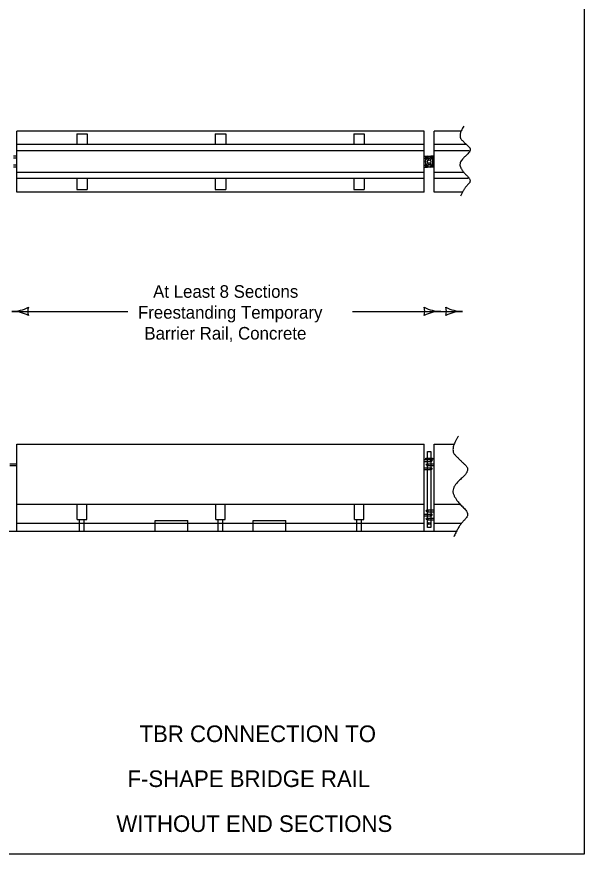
# Model space of a CAD drawing. Extents: x 10028 to 81668, y 3581 to 11018.
# Drawn here: x 16183 to 16868, y 7924 to 8934 of the extents above; entities that cross this region are included whole.
import ezdxf

# ---------------------------------------------------------------- set-up
doc = ezdxf.new("R2010")
doc.units = 0
for name, color, linetype in [('dsnCellsNorthArrow', 7, 'Continuous'), ('dsnTextTabulation', 7, 'Continuous'), ('Level 41', 7, 'Continuous'), ('Level 9', 7, 'Continuous'), ('SheetBorder', 7, 'Continuous')]:
    doc.layers.add(name, color=color, linetype=linetype)

msp = doc.modelspace()

# ---------------------------------------------------------------- linework, layer by layer
at = {"layer": 'dsnTextTabulation'}
for p, q in [((16674.6, 8796.1), (16183.1, 8796.1)), ((16183.1, 8722.4), (16183.1, 8796.1)), ((16674.6, 8722.4), (16674.6, 8796.1)), ((16719.2, 8796.1), (16686.5, 8796.1)), ((16686.5, 8722.4), (16686.5, 8796.1)), ((16674.6, 8779.8), (16183.1, 8779.8)), ((16725.7, 8779.8), (16686.5, 8779.8)), ((16674.6, 8772.4), (16183.1, 8772.4)), ((16728.6, 8772.4), (16686.5, 8772.4)), ((16674.6, 8746.2), (16183.1, 8746.2)), ((16674.6, 8738.8), (16183.1, 8738.8)), ((16722.7, 8746.2), (16686.5, 8746.2)), ((16727.7, 8738.8), (16686.5, 8738.8)), ((16674.6, 8722.4), (16183.1, 8722.4)), ((16720.8, 8722.4), (16686.5, 8722.4)), ((16177.1, 8578.7), (16317, 8578.7)), ((16588, 8578.7), (16720.5, 8578.7)), ((16183.1, 8313.9), (16183.1, 8418.5)), ((16183.1, 8418.5), (16674.6, 8418.5)), ((16674.6, 8313.9), (16674.6, 8418.5)), ((16686.5, 8313.9), (16686.5, 8418.5)), ((16686.5, 8418.5), (16710.9, 8418.5)), ((16183.1, 8346.4), (16674.6, 8346.4)), ((16686.5, 8346.4), (16717.9, 8346.4)), ((16183.1, 8323.4), (16674.6, 8323.4)), ((16350.2, 8326.7), (16389.5, 8326.7)), ((16350.2, 8313.6), (16350.2, 8323.4)), ((16389.5, 8313.6), (16389.5, 8323.4)), ((16468.1, 8326.7), (16507.5, 8326.7)), ((16468.1, 8313.6), (16468.1, 8323.4)), ((16507.5, 8313.6), (16507.5, 8323.4)), ((16686.5, 8323.4), (16719.4, 8323.4)), ((16183.3, 8313.6), (16350.2, 8313.6)), ((16389.5, 8313.6), (16468.1, 8313.6)), ((16507.5, 8313.6), (16674.3, 8313.6)), ((16686.7, 8313.6), (16713.5, 8313.6))]:
    msp.add_line(p, q, dxfattribs=at)
for centre, radius, start, end in [((16177.1, 8621.2), 42.5, 270, 298.0725), ((16177.1, 8536.2), 42.5, 61.9275, 90), ((16212.8, 8578.7), 16.4, 162.2666, 197.7334), ((16658.7, 8578.7), 16.4, 342.2666, 17.7333), ((16694.4, 8621.2), 42.5, 241.9275, 270), ((16694.4, 8536.2), 42.5, 90, 118.0725), ((16684.8, 8578.7), 16.4, 342.2666, 17.7333), ((16720.5, 8621.2), 42.5, 241.9275, 270), ((16720.5, 8536.2), 42.5, 90, 118.0725)]:
    msp.add_arc(centre, radius, start, end, dxfattribs=at)
at = {"layer": 'Level 41'}
for p, q in [((16255.4, 8793), (16268, 8793)), ((16255.4, 8793), (16255.4, 8779.8)), ((16268, 8793), (16268, 8779.8)), ((16422.5, 8793), (16435.1, 8793)), ((16422.5, 8793), (16422.5, 8779.8)), ((16435.1, 8793), (16435.1, 8779.8)), ((16589.7, 8793), (16589.7, 8779.8)), ((16589.7, 8793), (16602.2, 8793)), ((16602.2, 8793), (16602.2, 8779.8)), ((16183.1, 8766), (16179.1, 8766)), ((16183.1, 8763.6), (16179.1, 8763.6)), ((16674.6, 8766), (16678.5, 8766)), ((16674.6, 8763.6), (16678.5, 8763.6)), ((16686.5, 8766), (16682.5, 8766)), ((16686.5, 8763.6), (16682.5, 8763.6)), ((16183.1, 8755), (16179.1, 8755)), ((16183.1, 8752.6), (16179.1, 8752.6)), ((16674.6, 8755), (16678.5, 8755)), ((16674.6, 8752.6), (16678.5, 8752.6)), ((16686.5, 8755), (16682.5, 8755)), ((16686.5, 8752.6), (16682.5, 8752.6)), ((16255.4, 8738.8), (16255.4, 8725.5)), ((16268, 8738.8), (16268, 8725.5)), ((16422.5, 8738.8), (16422.5, 8725.5)), ((16435.1, 8738.8), (16435.1, 8725.5)), ((16589.7, 8738.8), (16589.7, 8725.5)), ((16602.2, 8738.8), (16602.2, 8725.5)), ((16255.4, 8725.5), (16268, 8725.5)), ((16422.5, 8725.5), (16435.1, 8725.5)), ((16589.7, 8725.5), (16602.2, 8725.5)), ((16174.6, 8394.9), (16183.1, 8394.9)), ((16674.6, 8399.9), (16683.1, 8399.9)), ((16674.6, 8397.7), (16683.1, 8397.7)), ((16678, 8394.9), (16686.5, 8394.9)), ((16174.6, 8392.8), (16183.1, 8392.8)), ((16674.6, 8390), (16683.1, 8390)), ((16674.6, 8387.9), (16683.1, 8387.9)), ((16678, 8392.8), (16686.5, 8392.8)), ((16256, 8327.8), (16256, 8346.4)), ((16267.4, 8327.8), (16267.4, 8346.4)), ((16423.2, 8327.8), (16423.2, 8346.4)), ((16434.5, 8327.8), (16434.5, 8346.4)), ((16590.3, 8327.8), (16590.3, 8346.4)), ((16601.6, 8327.8), (16601.6, 8346.4)), ((16674.6, 8334.3), (16683.1, 8334.3)), ((16678, 8339.2), (16686.5, 8339.2)), ((16678, 8337.1), (16686.5, 8337.1)), ((16256, 8327.8), (16267.4, 8327.8)), ((16258.9, 8313.6), (16258.9, 8327.8)), ((16264.5, 8313.6), (16264.5, 8327.8)), ((16423.2, 8327.8), (16434.5, 8327.8)), ((16426, 8313.6), (16426, 8327.8)), ((16431.7, 8313.6), (16431.7, 8327.8)), ((16590.3, 8327.8), (16601.6, 8327.8)), ((16593.1, 8313.6), (16593.1, 8327.8)), ((16598.8, 8313.6), (16598.8, 8327.8)), ((16674.6, 8332.2), (16683.1, 8332.2)), ((16678, 8329.4), (16686.5, 8329.4)), ((16678, 8327.3), (16686.5, 8327.3))]:
    msp.add_line(p, q, dxfattribs=at)
for centre in [(16678, 8393.9), (16683.1, 8398.8), (16683.1, 8389), (16678, 8338.2), (16683.1, 8333.3), (16678, 8328.4)]:
    msp.add_circle(centre, 1.06, dxfattribs=at)
for centre, radius, start, end in [((16682.5, 8759.3), 6.68, 90, 270), ((16682.5, 8759.3), 4.33, 90, 270), ((16678.5, 8759.3), 6.68, 270, 90), ((16678.5, 8759.3), 4.33, 270, 90)]:
    msp.add_arc(centre, radius, start, end, dxfattribs=at)
at = {"layer": 'Level 9'}
for p, q in [((16676.4, 8765.8), (16684.6, 8765.8)), ((16676.4, 8752.7), (16676.4, 8765.8)), ((16684.6, 8765.8), (16684.6, 8752.7)), ((16684.6, 8752.7), (16676.4, 8752.7)), ((16678.5, 8409.7), (16682.6, 8409.7)), ((16678.5, 8401.5), (16678.5, 8409.7)), ((16682.6, 8409.7), (16682.6, 8401.5)), ((16676.4, 8401.5), (16684.6, 8401.5)), ((16676.4, 8399.9), (16676.4, 8401.5)), ((16684.6, 8399.9), (16676.4, 8399.9)), ((16678.5, 8317.9), (16678.5, 8399.9)), ((16682.6, 8399.9), (16682.6, 8317.9)), ((16684.6, 8401.5), (16684.6, 8399.9)), ((16350.2, 8323.4), (16350.2, 8326.7)), ((16350.2, 8323.4), (16389.5, 8323.4)), ((16389.5, 8323.4), (16389.5, 8326.7)), ((16468.1, 8323.4), (16468.1, 8326.7)), ((16468.1, 8323.4), (16507.5, 8323.4)), ((16507.5, 8323.4), (16507.5, 8326.7)), ((13834.4, 8313.6), (16709.2, 8313.6)), ((16183.1, 8313.9), (16183.3, 8313.6)), ((16674.3, 8313.6), (16674.6, 8313.9)), ((16682.6, 8317.9), (16678.5, 8317.9)), ((16686.5, 8313.9), (16686.7, 8313.6))]:
    msp.add_line(p, q, dxfattribs=at)
for centre, radius in [((16680.5, 8759.3), 2.05), ((16680.5, 8322.9), 1.02)]:
    msp.add_circle(centre, radius, dxfattribs=at)
for points in [[(16722.2, 8801.9), (16714.9, 8790.7), (16723.9, 8781.3), (16732.9, 8773.2), (16715.7, 8758.6), (16720.5, 8747.5), (16732.4, 8736.4), (16723, 8727.8), (16718.3, 8717.5)], [(16715.7, 8428.4), (16705.2, 8412.3), (16718.2, 8398.8), (16731.1, 8387.1), (16706.5, 8366.1), (16713.2, 8350.1), (16730.5, 8334), (16716.9, 8321.7), (16710.2, 8306.9)]]:
    msp.add_open_spline(points, degree=2, dxfattribs=at)
at = {"layer": 'SheetBorder'}
msp.add_lwpolyline([(13732.5, 9944), (16867.5, 9944), (16867.5, 7924), (13732.5, 7924)], close=True, dxfattribs=at)

# ---------------------------------------------------------------- texts
at = {"layer": 'dsnCellsNorthArrow'}
for s, height, p in [('At Least 8 Sections', 15.2, (16347.5, 8595.1)), ('Freestanding Temporary', 15.2, (16329.2, 8569.9)), ('Barrier Rail, Concrete', 15.2, (16337, 8544.7)), ('TBR CONNECTION TO', 20, (16331.1, 8059.3)), ('F-SHAPE BRIDGE RAIL', 20, (16316.6, 8005.1)), ('WITHOUT END SECTIONS', 20, (16303.2, 7950.9))]:
    msp.add_text(s, height=height, dxfattribs=at).set_placement(p)

doc.saveas('drawing.dxf')
